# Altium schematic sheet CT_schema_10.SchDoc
size 274 x 160 mm
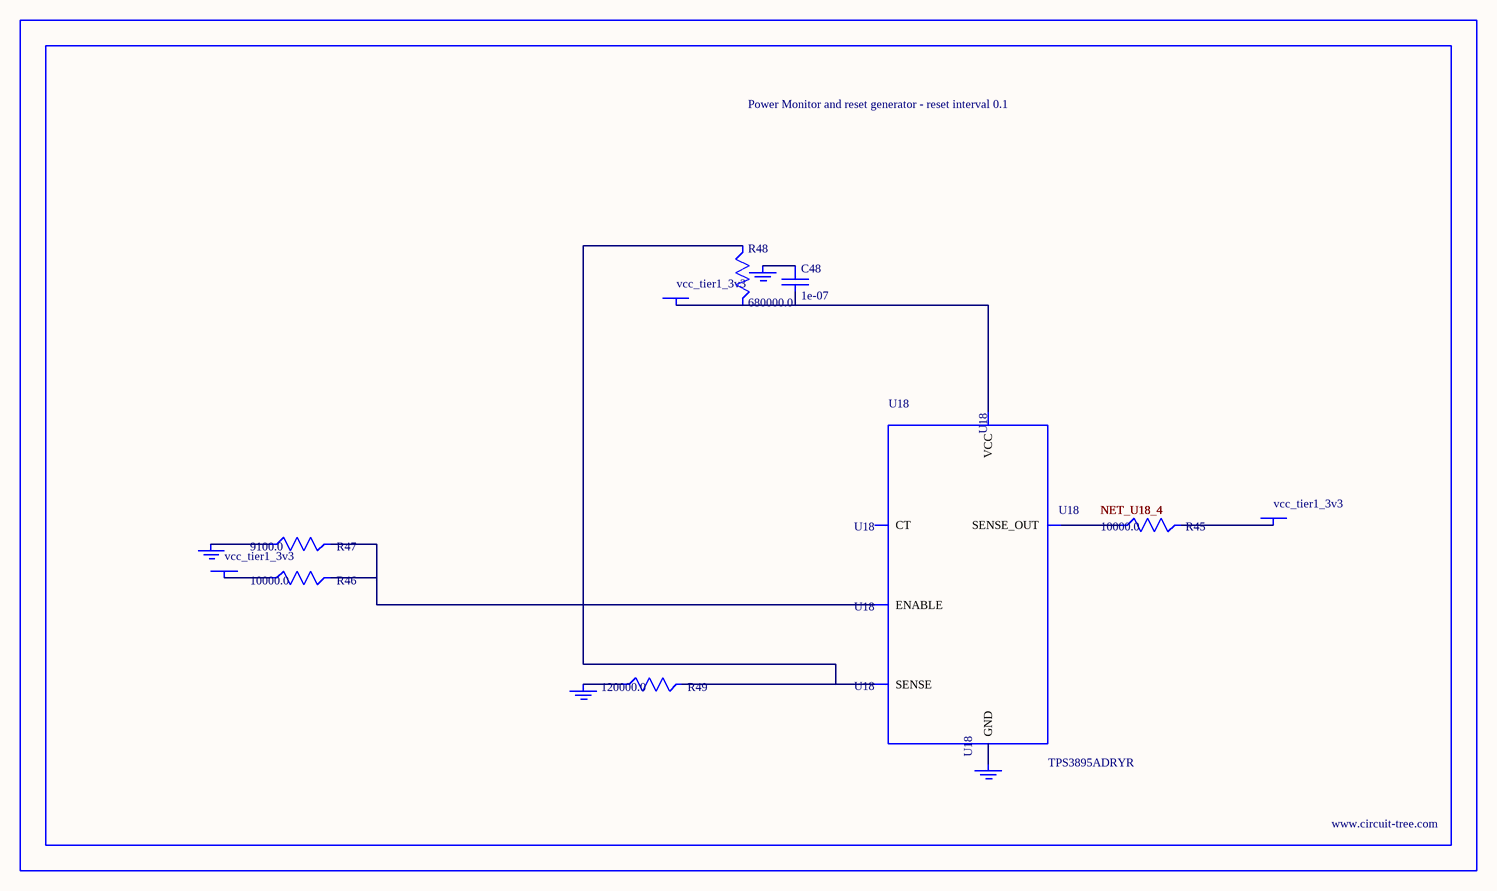
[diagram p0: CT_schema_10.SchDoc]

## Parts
BORDER9  (no value)
C48  1e-07  [C0402]
GND_INSTANCE_9_0  (no value)
GND_INSTANCE_9_1  (no value)
GND_INSTANCE_9_2  (no value)
GND_INSTANCE_9_3  (no value)
POWER_INSTANCE_9_0  vcc_tier1_3v3
POWER_INSTANCE_9_1  vcc_tier1_3v3
POWER_INSTANCE_9_2  vcc_tier1_3v3
R45  10000.0  [R0603]
R46  10000.0  [R0603]
R47  9100.0  [R0603]
R48  680000.0  [R0603]
R49  120000.0  [R0603]
U18  TPS3895ADRYR  [SON-6]

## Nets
NetC48_1: C48.1 GND_INSTANCE_9_2.0(GND)
NetC48_2: C48.2 POWER_INSTANCE_9_2.0(PWR) R48.2 U18.6(VCC)
NetGND_INSTANCE_9_0_0: GND_INSTANCE_9_0.0(GND) R47.1
NetGND_INSTANCE_9_1_0: GND_INSTANCE_9_1.0(GND) R49.1
NetGND_INSTANCE_9_3_0: GND_INSTANCE_9_3.0(GND) U18.2(GND)
NetPOWER_INSTANCE_9_0_0: POWER_INSTANCE_9_0.0(PWR) R46.1
NetPOWER_INSTANCE_9_1_0: POWER_INSTANCE_9_1.0(PWR) R45.2
NetR45_1: R45.1 U18.4(SENSE_OUT)
NetR46_2: R46.2 R47.2 U18.1(ENABLE)
NetR48_1: R48.1 R49.2 U18.3(SENSE)

Not connected (* = marked no-connect by the designer): U18 5(CT)

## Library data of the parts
BORDER9 = BORDER_PAGE9
C48 = C0402C104K3RACTU
GND_INSTANCE_9_0-GND_INSTANCE_9_3 = GND
POWER_INSTANCE_9_0-POWER_INSTANCE_9_2 = PWR
R45 R46 = RC0603JR-0710KL
R47 = RC0603JR-079K1L
R48 = RC0603JR-07680KL
R49 = RC0603JR-07120KL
